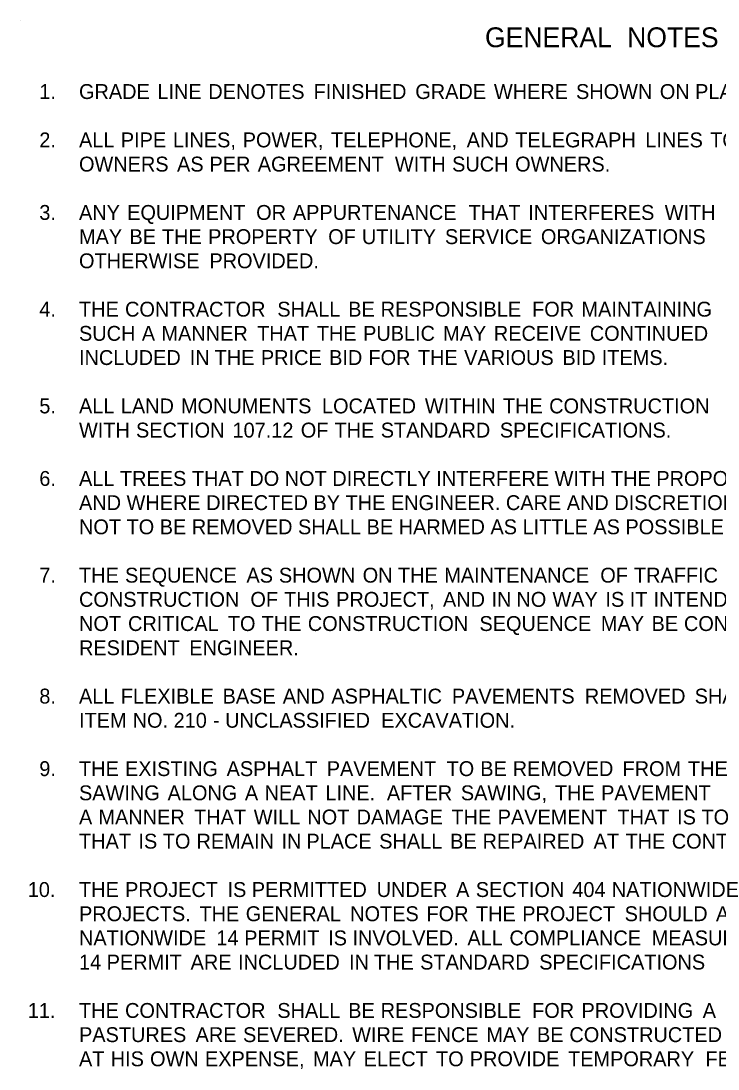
# Model space of a CAD drawing. Extents: x -1197 to 1681, y -1031 to 1021.
# Drawn here: x 358 to 920, y 14 to 860 of the extents above; entities that cross this region are included whole.
import ezdxf

# ---------------------------------------------------------------- set-up
doc = ezdxf.new("R2010")
doc.units = 0
doc.layers.add('Default', color=7, linetype='Continuous')

msp = doc.modelspace()

# ---------------------------------------------------------------- linework, layer by layer
at = {"layer": 'Default'}
msp.add_line((357.65, 859.58), (357.65, 859.58), dxfattribs=at)

# ---------------------------------------------------------------- texts
for s, height, p in [('GENERAL', 16, (731.73, 838.42)), (' NOTES', 16, (840.37, 838.42)), ('1.', 12, (372.44, 796.66)), ('GRADE', 12, (404.45, 796.66)), (' LINE', 12, (463.19, 796.66)), (' DENOTES', 12, (504.22, 796.66)), (' FINISHED', 12, (589.06, 796.66)), (' GRADE', 12, (671.08, 796.66)), (' WHERE', 12, (734.47, 796.66)), (' SHOWN', 12, (800.65, 796.66)), (' ON', 12, (868.2, 796.66)), (' PLANS.', 12, (896.64, 796.66)), ('2.', 12, (372.44, 757.66)), ('ALL', 12, (404.45, 757.66)), (' PIPE', 12, (433.69, 757.66)), (' LINES,', 12, (475.66, 757.66)), (' POWER,', 12, (531.94, 757.66)), (' TELEPHONE,', 12, (603.1, 757.66)), (' AND', 12, (712.49, 757.66)), (' TELEGRAPH', 12, (751.66, 757.66)), (' LINES', 12, (856.53, 757.66)), (' TO', 12, (908.77, 757.66)), ('OWNERS', 12, (404.45, 738.16)), (' AS', 12, (479.03, 738.16)), (' PER', 12, (505.18, 738.16)), (' AGREEMENT', 12, (544.09, 738.16)), (' WITH', 12, (654.63, 738.16)), (' SUCH', 12, (700.76, 738.16)), (' OWNERS.', 12, (751.58, 738.16)), ('3.', 12, (372.44, 699.16)), ('ANY', 12, (404.45, 699.16)), (' EQUIPMENT', 12, (438.81, 699.16)), (' OR', 12, (542.81, 699.16)), (' APPURTENANCE', 12, (572.39, 699.16)), (' THAT', 12, (714.06, 699.16)), (' INTERFERES', 12, (762.16, 699.16)), (' WITH', 12, (872.15, 699.16)), ('MAY', 12, (404.45, 679.66)), (' BE', 12, (440.66, 679.66)), (' THE', 12, (466.8, 679.66)), (' PROPERTY', 12, (504.09, 679.66)), (' OF', 12, (600.87, 679.66)), (' UTILITY', 12, (628.05, 679.66)), (' SERVICE', 12, (694.99, 679.66)), (' ORGANIZATIONS', 12, (772.37, 679.66)), ('OTHERWISE', 12, (404.45, 660.16)), (' PROVIDED.', 12, (505.1, 660.16)), ('4.', 12, (372.44, 621.16)), ('THE', 12, (404.45, 621.16)), (' CONTRACTOR', 12, (437.1, 621.16)), (' SHALL', 12, (559.83, 621.16)), (' BE', 12, (617.02, 621.16)), (' RESPONSIBLE', 12, (643.15, 621.16)), (' FOR', 12, (765.26, 621.16)), (' MAINTAINING', 12, (805.08, 621.16)), ('SUCH', 12, (404.45, 601.66)), (' A', 12, (450.62, 601.66)), (' MANNER', 12, (466.49, 601.66)), (' THAT', 12, (543.58, 601.66)), (' THE', 12, (591.68, 601.66)), (' PUBLIC', 12, (628.98, 601.66)), (' MAY', 12, (693.53, 601.66)), (' RECEIVE', 12, (734.4, 601.66)), (' CONTINUED', 12, (811.78, 601.66)), ('INCLUDED', 12, (404.45, 582.16)), (' IN', 12, (489.27, 582.16)), (' THE', 12, (509.32, 582.16)), (' PRICE', 12, (546.62, 582.16)), (' BID', 12, (601.62, 582.16)), (' FOR', 12, (633.33, 582.16)), (' THE', 12, (673.16, 582.16)), (' VARIOUS', 12, (710.45, 582.16)), (' BID', 12, (789.71, 582.16)), (' ITEMS.', 12, (821.42, 582.16)), ('5.', 12, (372.44, 543.16)), ('ALL', 12, (404.45, 543.16)), (' LAND', 12, (433.69, 543.16)), (' MONUMENTS', 12, (482.17, 543.16)), (' LOCATED', 12, (595.87, 543.16)), (' WITHIN', 12, (678.83, 543.16)), (' THE', 12, (741.71, 543.16)), (' CONSTRUCTION', 12, (779.01, 543.16)), ('WITH', 12, (404.45, 523.66)), (' SECTION', 12, (445.93, 523.66)), (' 107.12', 12, (523.75, 523.66)), (' OF', 12, (578.77, 523.66)), (' THE', 12, (605.95, 523.66)), (' STANDARD', 12, (643.25, 523.66)), (' SPECIFICATIONS.', 12, (739.25, 523.66)), ('6.', 12, (372.44, 484.66)), ('ALL TREES THAT DO NOT DIRECTLY INTERFERE WITH THE PROPOSED CONSTRUCTION SHALL BE SPARED IF', 12, (404.45, 484.66)), ('AND WHERE DIRECTED BY THE ENGINEER. CARE AND DISCRETION SHALL BE USED TO ENSURE THAT ALL TREES  ', 12, (404.45, 465.16)), ('NOT TO BE REMOVED SHALL BE HARMED AS LITTLE AS POSSIBLE DURING THE CONSTRUCTION OPERATIONS.', 12, (404.45, 445.66)), ('7.', 12, (372.44, 406.66)), ('THE', 12, (404.45, 406.66)), (' SEQUENCE', 12, (437.1, 406.66)), (' AS', 12, (534.97, 406.66)), (' SHOWN', 12, (561.12, 406.66)), (' ON', 12, (628.68, 406.66)), (' THE', 12, (657.11, 406.66)), (' MAINTENANCE', 12, (694.41, 406.66)), (' OF', 12, (820.22, 406.66)), (' TRAFFIC', 12, (847.39, 406.66)), ('CONSTRUCTION', 12, (404.45, 387.16)), (' OF', 12, (538.16, 387.16)), (' THIS', 12, (565.33, 387.16)), (' PROJECT,', 12, (607.3, 387.16)), (' AND', 12, (693.39, 387.16)), (' IN', 12, (732.55, 387.16)), (' NO', 12, (752.6, 387.16)), (' WAY', 12, (781.66, 387.16)), (' IS', 12, (824.38, 387.16)), (' IT', 12, (844, 387.16)), (' INTENDED', 12, (863.22, 387.16)), ('NOT', 12, (404.45, 367.66)), (' CRITICAL', 12, (439.51, 367.66)), (' TO', 12, (519.96, 367.66)), (' THE', 12, (547.16, 367.66)), (' CONSTRUCTION', 12, (584.45, 367.66)), (' SEQUENCE', 12, (722.81, 367.66)), (' MAY', 12, (820.69, 367.66)), (' BE', 12, (861.55, 367.66)), (' CONSTRUCTED', 12, (887.68, 367.66)), ('RESIDENT', 12, (404.45, 348.16)), (' ENGINEER.', 12, (488.9, 348.16)), ('8.', 12, (372.44, 309.16)), (' BASE', 12, (515.73, 309.16)), (' ASPHALTIC', 12, (603.4, 309.16)), (' PAVEMENTS', 12, (700.57, 309.16)), (' REMOVED', 12, (807.78, 309.16)), (' SHALL', 12, (896.33, 309.16)), ('ALL', 12, (404.45, 309.16)), (' FLEXIBLE', 12, (433.69, 309.16)), (' AND', 12, (564.23, 309.16)), ('ITEM', 12, (404.45, 289.66)), (' NO.', 12, (443.24, 289.66)), (' 210', 12, (476.24, 289.66)), (' UNCLASSIFIED', 12, (517.77, 289.66)), (' EXCAVATION.', 12, (643.59, 289.66)), (' -', 12, (508.06, 289.66)), ('9.', 12, (372.44, 250.66)), ('THE', 12, (404.45, 250.66)), (' EXISTING', 12, (437.1, 250.66)), (' ASPHALT', 12, (518.97, 250.66)), (' PAVEMENT', 12, (599.7, 250.66)), (' TO', 12, (696.27, 250.66)), (' BE', 12, (723.46, 250.66)), (' REMOVED', 12, (749.59, 250.66)), (' FROM', 12, (838.14, 250.66)), (' THE', 12, (890.89, 250.66)), ('SAWING', 12, (404.45, 231.16)), (' ALONG', 12, (471.41, 231.16)), (' A', 12, (533.71, 231.16)), (' NEAT', 12, (549.58, 231.16)), (' LINE.', 12, (598.62, 231.16)), ('  AFTER', 12, (643.74, 231.16)), (' SAWING,', 12, (707.79, 231.16)), (' THE', 12, (783.62, 231.16)), (' PAVEMENT', 12, (820.91, 231.16)), ('A', 12, (404.45, 211.66)), (' MANNER', 12, (415.67, 211.66)), (' THAT', 12, (492.76, 211.66)), (' WILL', 12, (540.86, 211.66)), (' NOT', 12, (584.04, 211.66)), (' DAMAGE', 12, (623.76, 211.66)), (' THE', 12, (700.19, 211.66)), (' PAVEMENT', 12, (737.49, 211.66)), (' THAT', 12, (834.06, 211.66)), (' IS', 12, (882.16, 211.66)), (' TO', 12, (901.78, 211.66)), ('THAT', 12, (404.45, 192.16)), (' IS', 12, (447.9, 192.16)), (' TO', 12, (467.52, 192.16)), (' REMAIN', 12, (494.71, 192.16)), (' IN', 12, (563.21, 192.16)), (' PLACE', 12, (583.26, 192.16)), (' SHALL', 12, (642, 192.16)), (' BE', 12, (699.19, 192.16)), (' REPAIRED', 12, (725.32, 192.16)), (' AT', 12, (814.81, 192.16)), (' THE', 12, (840.55, 192.16)), (" CONTRACTOR'S", 12, (877.85, 192.16)), ('10.', 12, (363.12, 153.16)), ('THE', 12, (404.45, 153.16)), (' PROJECT', 12, (437.1, 153.16)), (' IS', 12, (519.68, 153.16)), (' PERMITTED', 12, (539.3, 153.16)), (' UNDER', 12, (639.95, 153.16)), (' A', 12, (704, 153.16)), (' SECTION', 12, (719.87, 153.16)), (' 404', 12, (797.68, 153.16)), (' NATIONWIDE', 12, (829.49, 153.16)), ('PROJECTS.', 12, (404.45, 133.66)), (' THE', 12, (497.1, 133.66)), (' GENERAL', 12, (534.4, 133.66)), (' NOTES', 12, (618.6, 133.66)), (' FOR', 12, (680.14, 133.66)), (' THE', 12, (719.97, 133.66)), (' PROJECT', 12, (757.27, 133.66)), (' SHOULD', 12, (839.85, 133.66)), (' ALERT', 12, (913.49, 133.66)), ('NATIONWIDE', 12, (404.45, 114.16)), (' 14', 12, (510.68, 114.16)), (' PERMIT', 12, (533.16, 114.16)), (' IS', 12, (600.83, 114.16)), (' INVOLVED.', 12, (620.45, 114.16)), (' ALL', 12, (713.09, 114.16)), (' COMPLIANCE', 12, (746.98, 114.16)), (' MEASURES', 12, (861.61, 114.16)), ('14', 12, (404.45, 94.66)), (' PERMIT', 12, (422.28, 94.66)), (' ARE', 12, (489.95, 94.66)), (' INCLUDED', 12, (528.19, 94.66)), (' IN', 12, (617.66, 94.66)), (' THE', 12, (637.7, 94.66)), (' STANDARD', 12, (675, 94.66)), (' SPECIFICATIONS', 12, (771, 94.66)), ('11.', 12, (363.12, 55.66)), ('THE', 12, (404.45, 55.66)), (' CONTRACTOR', 12, (437.1, 55.66)), (' SHALL', 12, (559.83, 55.66)), (' BE', 12, (617.02, 55.66)), (' RESPONSIBLE', 12, (643.15, 55.66)), (' FOR', 12, (765.26, 55.66)), (' PROVIDING', 12, (805.08, 55.66)), (' A', 12, (902.78, 55.66)), ('PASTURES', 12, (404.45, 36.16)), (' ARE', 12, (493.97, 36.16)), (' SEVERED.', 12, (532.21, 36.16)), (' WIRE', 12, (620.21, 36.16)), (' FENCE', 12, (667.74, 36.16)), (' MAY', 12, (728.34, 36.16)), (' BE', 12, (769.2, 36.16)), (' CONSTRUCTED', 12, (795.33, 36.16)), ('AT', 12, (404.45, 16.66)), (' HIS', 12, (425.55, 16.66)), (' OWN', 12, (457.27, 16.66)), (' EXPENSE,', 12, (501.53, 16.66)), (' MAY', 12, (588.58, 16.66)), (' ELECT', 12, (629.45, 16.66)), (' TO', 12, (687.81, 16.66)), (' PROVIDE', 12, (715, 16.66)), (' TEMPORARY', 12, (794.24, 16.66)), (' FENCING', 12, (904.98, 16.66))]:
    msp.add_text(s, height=height, dxfattribs=at).set_placement(p)

doc.saveas('drawing.dxf')
